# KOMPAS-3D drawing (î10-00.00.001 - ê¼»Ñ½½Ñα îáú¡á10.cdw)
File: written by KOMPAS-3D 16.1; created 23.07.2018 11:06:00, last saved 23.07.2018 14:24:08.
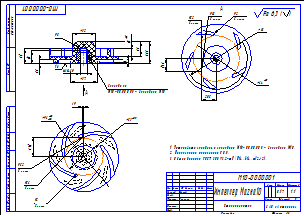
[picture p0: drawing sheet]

Sheet 1: A3, landscape

Title block, sheet 1: name: Импеллер Магна10; designation: М10-00.00.001; mass: 0,17; scale: 1:1; sheets: 1; organisation: ЗАО «Астерион»; sheet format: A3; stored path: Z:\Магна\Магна Ins\Магна ins 10\М10-00.00.000\3Д\М10-00.00.001 - Импеллер Магна10.cdw; drawn by: Милов; technical control: Лучихин

Views: Вид 1, Спереди, Проекционный вид 3, Местный разрез 1, Вид по стрелке 4
Referenced files in Z:\Магна\Магна Ins\Магна ins 10\М10-00.00.000\3Д\: М10-00.00.001 - Импеллер Магна10.m3d, М10-00.00.005 - Закладная М10.m3d
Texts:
  Стеклопластик
  Закладная
  М10-00.00.005 - Закладная М10
  Установить заподлицо закладную М10-00.00.005 - Закладная М10.
  Неуказанные скругления R0,5.
  Общие допуски ГОСТ 30893.2-mK (H14, h14,  t2/2).
  Ra 6,3
  Ra 6,3 ( )
  Закладная М10
Dimensions and other numbers on the sheet: 53; 52; 5 мест; 56; 1,9; 27,1; 2; 96; 10; 4; 5,5; 21; 32; 20; 30,5; 8; 37; 1,6; -6Н; 18; 64; 20,5; 17,9; 86; 1:1; 1; 0,17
